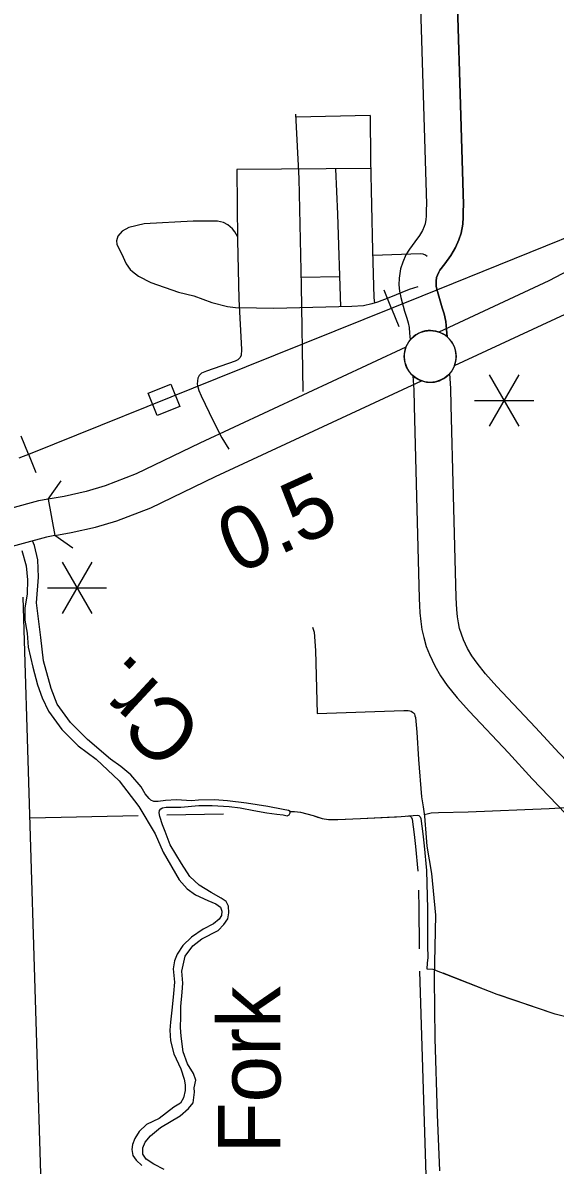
# Model space of a CAD drawing. Extents: x 1084508 to 1142749, y 1057638 to 1093403.
# Drawn here: x 1109506 to 1110633, y 1075928 to 1078349 of the extents above; entities that cross this region are included whole.
import ezdxf

# ---------------------------------------------------------------- set-up
doc = ezdxf.new("R2010")
doc.units = 0
for name, color, linetype in [('Level 10', 7, 'Continuous'), ('Level 15', 7, 'Continuous'), ('Level 2', 7, 'Continuous'), ('Level 24', 7, 'Continuous'), ('Level 33', 7, 'Continuous'), ('Level 34', 7, 'Continuous'), ('Level 35', 7, 'Continuous'), ('Level 37', 7, 'Continuous'), ('Level 40', 7, 'Continuous'), ('Level 43', 7, 'Continuous'), ('Level 48', 7, 'Continuous'), ('Level 6', 7, 'Continuous')]:
    doc.layers.add(name, color=color, linetype=linetype)

msp = doc.modelspace()

# ---------------------------------------------------------------- linework, layer by layer
at = {"layer": 'Level 10'}
for p, q in [((1110360.1, 1077952.2), (1110360.1, 1077950.4)), ((1110438.5, 1077948.6), (1110438.5, 1077950.4))]:
    msp.add_line(p, q, dxfattribs=at)
for points in [[(1110347.9, 1078381.2), (1110354.3, 1078172.5), (1110360.6, 1077964.2), (1110360.1, 1077952.2)], [(1110426.3, 1078384.2), (1110432.8, 1078174.9), (1110439.2, 1077963.6), (1110438.5, 1077948.6)], [(1110438.5, 1077948.6), (1110439.2, 1077963.6), (1110432.8, 1078174.9), (1110426.3, 1078384.2)], [(1110360.1, 1077950.4), (1110360.1, 1077939), (1110359.7, 1077932.1), (1110357.9, 1077922.9), (1110355.9, 1077916.8), (1110352.1, 1077908.3), (1110346.1, 1077898.1), (1110336.2, 1077884.3), (1110324.9, 1077869.2), (1110317.1, 1077857.2), (1110310.6, 1077841.6), (1110305.6, 1077827), (1110303, 1077807.7), (1110302.5, 1077793.4), (1110303.8, 1077779.7), (1110306.3, 1077766.4), (1110314.5, 1077737.6), (1110318.8, 1077722.9), (1110321.8, 1077712.6), (1110323.8, 1077703.2), (1110325.1, 1077690.9), (1110326.3, 1077676.6)], [(1110438.5, 1077950.4), (1110438.5, 1077936.7), (1110437.7, 1077922.2), (1110434, 1077903.2), (1110429.2, 1077888.5), (1110422, 1077872.5), (1110412.1, 1077855.3), (1110399.4, 1077837.8), (1110389.3, 1077824.2), (1110386.7, 1077820.3), (1110384, 1077813.8), (1110382.3, 1077808.8), (1110381.3, 1077801.2), (1110381.1, 1077796), (1110381.6, 1077790.7), (1110382.8, 1077784.4), (1110389.9, 1077759.3), (1110394.2, 1077744.7), (1110397.9, 1077731.7), (1110401.4, 1077715.5), (1110403.2, 1077698.4), (1110404.5, 1077683.2)], [(1110404.5, 1077683.2), (1110403.2, 1077698.4), (1110401.4, 1077715.5), (1110397.9, 1077731.7), (1110394.2, 1077744.7), (1110389.9, 1077759.3), (1110382.8, 1077784.4), (1110381.6, 1077790.7), (1110381.1, 1077796), (1110381.3, 1077801.2), (1110382.3, 1077808.8), (1110384, 1077813.8), (1110386.7, 1077820.3), (1110389.3, 1077824.2), (1110399.4, 1077837.8), (1110412.1, 1077855.3), (1110422, 1077872.5), (1110429.2, 1077888.5), (1110434, 1077903.2), (1110437.7, 1077922.2), (1110438.5, 1077936.7), (1110438.5, 1077950.4)], [(1110331.9, 1077600.8), (1110333.8, 1077570.7), (1110334.4, 1077535.9), (1110339.6, 1077344.8), (1110345.4, 1077128.6), (1110345.7, 1077113.8), (1110346.7, 1077098.3), (1110348.7, 1077080), (1110351.1, 1077063.1), (1110354.8, 1077045.6), (1110360.4, 1077027.1), (1110367.2, 1077009.8), (1110378.2, 1076986), (1110390.6, 1076964.7), (1110404.8, 1076944.3), (1110425.6, 1076918.2), (1110451.8, 1076889.2), (1110534.2, 1076801.5), (1110584.8, 1076746.7), (1110673.9, 1076653.8), (1110852.9, 1076463), (1111028.2, 1076276), (1111170.9, 1076126.4)], [(1111170.9, 1076126.4), (1111167.8, 1076243.4), (1111085.2, 1076329.9), (1110910.1, 1076516.7), (1110730.8, 1076707.9), (1110641.9, 1076800.4), (1110591.6, 1076855), (1110509.5, 1076942.3), (1110485.5, 1076968.9), (1110467.8, 1076991.2), (1110456.9, 1077006.9), (1110447.9, 1077022.3), (1110439.3, 1077040.7), (1110434.6, 1077052.8), (1110430.9, 1077064.9), (1110428.5, 1077076.7), (1110426.6, 1077089.8), (1110424.9, 1077105.2), (1110424.1, 1077117.2), (1110423.8, 1077130.5), (1110418, 1077346.9), (1110412.8, 1077537.6), (1110412.2, 1077573.8), (1110410.2, 1077605.7)]]:
    msp.add_lwpolyline(points, dxfattribs=at)
for start, end in [(49.2235, 140.3932), (228.0122, 319.182)]:
    msp.add_arc((1110368.6, 1077641.6), 54.9, start, end, dxfattribs=at)
at = {"layer": 'Level 15'}
msp.add_line((1109559.6, 1077339.2), (1109573.2, 1077261.9), dxfattribs=at)
for points in [[(1118020.1, 1080804.8), (1117454.8, 1080577.1), (1116519.3, 1080199.4), (1116394.7, 1080147.6), (1116308.1, 1080104.8), (1116151.2, 1080024.8), (1116076, 1079990.7), (1115983.7, 1079954.5), (1115857.6, 1079915.5), (1115726, 1079874.6), (1115624.4, 1079837.7), (1114621, 1079433.2), (1113651.5, 1079041.6), (1112659, 1078640), (1111665.4, 1078240.4), (1110770, 1077877.8), (1110703.6, 1077845.6), (1110619.8, 1077801.6), (1110387, 1077693.4)], [(1110420, 1077622.2), (1110654.6, 1077731.3), (1110738.9, 1077775.5), (1110801.9, 1077806.1), (1111694.8, 1078167.6), (1112688.3, 1078567.2), (1113680.9, 1078968.8), (1114650.4, 1079360.4), (1115652.5, 1079764.4), (1115751, 1079800.2), (1115880.8, 1079840.5), (1116009.6, 1079880.4), (1116106.5, 1079918.4), (1116185.3, 1079954.1), (1116343.3, 1080034.7), (1116427.2, 1080076.1), (1116549, 1080126.8), (1117484.2, 1080504.3), (1118049.4, 1080732)], [(1110317.2, 1077661), (1109880.3, 1077457.9), (1109745.8, 1077392.6), (1109679.8, 1077367.7), (1109639.5, 1077355.5), (1109592.9, 1077345.1), (1109559.6, 1077339.2)], [(1109573.2, 1077261.9), (1109608.3, 1077268.1), (1109659.5, 1077279.6), (1109705, 1077293.4), (1109776.9, 1077320.4), (1109914, 1077387), (1110350.3, 1077589.8)], [(1109559.6, 1077339.2), (1109538.7, 1077335.5), (1109344.5, 1077282.5)], [(1109573.2, 1077261.9), (1109555.8, 1077258.8), (1109365.1, 1077206.8)]]:
    msp.add_lwpolyline(points, dxfattribs=at)
for start, end in [(339.3435, 70.5125), (159.3433, 250.5128)]:
    msp.add_arc((1110368.6, 1077641.6), 54.9, start, end, dxfattribs=at)
at = {"layer": 'Level 2'}
msp.add_lwpolyline([(1109611.1, 1072552.7), (1109576.8, 1074143.1), (1109546.8, 1075817.6), (1109506.3, 1077131.6)], dxfattribs=at)
at = {"layer": 'Level 24'}
msp.add_circle((1110368.6, 1077641.6), 54.9, dxfattribs=at)
at = {"layer": 'Level 33'}
for points in [[(1110083.4, 1078155), (1110090.3, 1078019), (1110095.2, 1077791), (1110098.8, 1077568.2), (1110098.8, 1077567.5)], [(1110241.3, 1078152.6), (1110083.7, 1078148.6)], [(1110241.3, 1078152.6), (1110242.2, 1078058.6), (1110246.6, 1077866.2), (1110249.1, 1077766.3), (1110250.3, 1077754.4)], [(1109959, 1078038.1), (1109960.4, 1077888.2), (1109963.3, 1077763.2), (1109968.9, 1077656.6), (1109968, 1077643.6), (1109965, 1077638.5), (1109960.8, 1077634.5), (1109955.4, 1077631.5), (1109894.5, 1077610.5)], [(1110242.6, 1078039.6), (1109959, 1078038.1)], [(1110179.2, 1077746.8), (1110173.1, 1077942.9), (1110168.8, 1078039.2)], [(1110362.3, 1077853.6), (1110358.4, 1077856.2), (1110353.7, 1077858.1), (1110347.9, 1077858.8), (1110246.8, 1077855.9)], [(1110094.8, 1077809.3), (1110177.2, 1077810.7)], [(1110342.4, 1077788.8), (1110323.8, 1077783.5), (1110280.7, 1077765.5), (1110257.2, 1077756.4), (1110244.9, 1077752.8), (1110227.4, 1077749.2), (1110202.5, 1077747.4), (1110037.2, 1077743), (1109963.9, 1077744.6)]]:
    msp.add_lwpolyline(points, dxfattribs=at)
at = {"layer": 'Level 34'}
for points in [[(1109960.3, 1077896), (1109954.6, 1077906), (1109949.6, 1077912.1), (1109939.9, 1077920.7), (1109930.6, 1077925.4), (1109918.1, 1077928.6), (1109866.5, 1077928.2), (1109762.6, 1077922.9), (1109730.4, 1077914.6), (1109716.1, 1077907.1), (1109706.8, 1077896.7), (1109704.2, 1077886.7), (1109705, 1077879.9), (1109708.2, 1077872), (1109714.3, 1077859.8), (1109724.7, 1077837.9), (1109732.9, 1077825.8), (1109737.6, 1077821.5), (1109750.8, 1077811.8), (1109777, 1077798.2), (1109835.3, 1077777.7), (1109867.9, 1077770.2), (1109906.3, 1077756.2), (1109939.2, 1077747.6), (1109956, 1077745.5), (1109963.9, 1077744.6)], [(1109894.5, 1077610.5), (1109883.9, 1077606.2), (1109879.3, 1077601.4), (1109876.5, 1077595.5), (1109875.4, 1077589.6), (1109875.1, 1077582.8), (1109876.2, 1077577.2), (1109878.8, 1077569.1), (1109883.7, 1077558), (1109900.5, 1077523), (1109921.4, 1077479.8), (1109927.4, 1077469.1), (1109942, 1077444.9)], [(1110119.6, 1077068.1), (1110123.1, 1077057.3), (1110125.9, 1077018.6), (1110129.2, 1076884.7), (1110312.7, 1076891.2), (1110322.1, 1076891.2), (1110325.8, 1076890.8), (1110328.2, 1076889.6), (1110331.1, 1076888), (1110333.1, 1076886.3), (1110335.2, 1076883.9), (1110336.4, 1076880.2), (1110337.6, 1076876.1), (1110340.1, 1076845.1), (1110344, 1076787.5), (1110350.1, 1076708.3), (1110353.4, 1076686.7), (1110356.2, 1076667.5), (1110359.9, 1076621.8), (1110361.5, 1076603.5), (1110371.3, 1076546), (1110379.5, 1076457.4), (1110377, 1076323.1), (1110378.5, 1076195.9), (1110383.3, 1076035.2), (1110388.4, 1075915.2)], [(1110688, 1076695.8), (1110684.3, 1076692.1), (1110679.2, 1076688.9), (1110673, 1076686.5), (1110666.6, 1076685.7), (1110656.1, 1076684.6), (1110620.9, 1076682.5), (1110448.7, 1076676), (1110386.3, 1076674.1), (1110371, 1076673.3), (1110362.1, 1076671.7), (1110355.8, 1076670.3)]]:
    msp.add_lwpolyline(points, dxfattribs=at)
at = {"layer": 'Level 35'}
for points in [[(1109804.9, 1075918.5), (1109783.3, 1075929.3), (1109766.7, 1075940.2), (1109759.9, 1075951), (1109759.9, 1075964.1), (1109764.5, 1075976.1), (1109776.4, 1075989.8), (1109797.5, 1076007.4), (1109839.1, 1076031.9), (1109856.8, 1076047.9), (1109866.5, 1076059.3), (1109869.3, 1076082.1), (1109868.7, 1076091.4), (1109872.2, 1076108), (1109867, 1076121.6), (1109854.5, 1076142.2), (1109845.4, 1076167.8), (1109840.8, 1076200.9), (1109839.7, 1076219.1), (1109840.2, 1076241.9), (1109840.2, 1076263.6), (1109843.1, 1076294.4), (1109844.8, 1076313.2), (1109842.5, 1076338.9), (1109849.4, 1076370.8), (1109865.9, 1076392.5), (1109884.7, 1076407.3), (1109919.5, 1076425), (1109931.4, 1076437.5), (1109940, 1076449.5), (1109941.7, 1076462.6), (1109941.1, 1076476.3), (1109936.6, 1076486.5), (1109925.7, 1076493.4), (1109904.6, 1076505.3), (1109879, 1076521.3), (1109859.1, 1076539.6), (1109842, 1076566.9), (1109818, 1076606.8), (1109807.2, 1076634.8), (1109801.5, 1076649), (1109795.8, 1076666.7), (1109794.5, 1076674.3), (1109795.1, 1076679.1), (1109797.7, 1076682.5), (1109801.4, 1076684.8), (1109809, 1076686.2), (1109840.1, 1076686.2), (1109878.3, 1076689.6), (1109906.8, 1076689.6), (1109942.4, 1076687.4), (1109965.8, 1076684.8), (1109995.2, 1076679.4), (1110022.3, 1076674.3), (1110043.4, 1076671.4), (1110056.8, 1076670), (1110065.9, 1076667.7), (1110069.6, 1076670), (1110071.6, 1076674), (1110071.6, 1076677.1), (1110068.5, 1076679.4), (1110057.1, 1076681.7), (1110024.3, 1076687.7), (1109979.3, 1076694.8), (1109939.1, 1076699.9), (1109912, 1076701.6), (1109878.1, 1076700.8), (1109862.7, 1076699.9), (1109831.4, 1076701.9), (1109808.2, 1076700.5), (1109792, 1076698.5), (1109782.8, 1076698.5), (1109776.6, 1076700.8), (1109772.9, 1076704.8), (1109764.9, 1076714.4), (1109756.6, 1076729.3), (1109734.7, 1076754.6), (1109713, 1076772.3), (1109691.1, 1076788.3), (1109642.8, 1076830), (1109606.9, 1076866), (1109578.4, 1076904.7), (1109565.9, 1076937.8), (1109549.3, 1076996.5), (1109543.6, 1077045.6), (1109534.5, 1077119.1), (1109538.5, 1077173.8), (1109537.4, 1077210.3), (1109530, 1077241.2), (1109526.4, 1077250.6)], [(1109503.2, 1077230.6), (1109512.9, 1077197.5), (1109515.2, 1077167.9), (1109514.6, 1077138.8), (1109510, 1077108.4), (1109509.5, 1077082.8), (1109514.6, 1077055.4), (1109516.9, 1077025.7), (1109527.1, 1076983), (1109536.8, 1076945.9), (1109546.5, 1076918), (1109560.2, 1076889.5), (1109588.1, 1076850.7), (1109622.9, 1076816.5), (1109661.3, 1076787.8), (1109709.8, 1076742.2), (1109751.4, 1076687.5), (1109786.1, 1076629.9), (1109802.7, 1076591.1), (1109836.9, 1076532.4), (1109854, 1076513.4), (1109871.1, 1076500.8), (1109897.8, 1076488.3), (1109914.4, 1076481.4), (1109924.6, 1076474), (1109926.9, 1076466), (1109926.3, 1076456.9), (1109921.2, 1076448.9), (1109909.8, 1076439.2), (1109887.6, 1076427.8), (1109863.1, 1076410.7), (1109844.8, 1076393.1), (1109832.9, 1076374.8), (1109826.6, 1076360.6), (1109823.8, 1076343.5), (1109826.6, 1076315.5), (1109824.9, 1076291.6), (1109822, 1076262.3), (1109818.1, 1076230.9), (1109816.9, 1076213.8), (1109818.1, 1076191), (1109825.5, 1076163.6), (1109840.3, 1076131.7), (1109847.7, 1076109.5)], [(1109847.7, 1076109.5), (1109849.4, 1076097.5), (1109849.4, 1076085.5), (1109846, 1076070.1), (1109839.7, 1076059.2), (1109825.5, 1076050.6), (1109794.1, 1076026.7), (1109767.9, 1076013.6), (1109751.9, 1075998.7), (1109742.8, 1075983.9), (1109737.7, 1075971.4), (1109736.6, 1075960.5), (1109738.3, 1075948), (1109745.7, 1075938.3), (1109757.6, 1075926.9)]]:
    msp.add_lwpolyline(points, dxfattribs=at)
at = {"layer": 'Level 37'}
for points in [[(1109559.6, 1077339.2), (1109586.6, 1077377.7)], [(1109611.8, 1077234.9), (1109573.2, 1077261.9)]]:
    msp.add_lwpolyline(points, dxfattribs=at)
at = {"layer": 'Level 40'}
for p, q in [((1110286.6, 1077743.5), (1110271.1, 1077781.9)), ((1110286.6, 1077743.5), (1110302, 1077705)), ((1109517.8, 1077434.2), (1109502.3, 1077472.6)), ((1109517.8, 1077434.2), (1109533.4, 1077395.8))]:
    msp.add_line(p, q, dxfattribs=at)
msp.add_lwpolyline([(1114164.2, 1079308.5), (1113746.2, 1079140.3), (1113322.1, 1078969), (1112887, 1078794.2), (1112466, 1078623.7), (1112227.5, 1078528), (1112039.2, 1078452), (1111631.7, 1078288.6), (1111182.3, 1078105.9), (1110742, 1077927.6), (1110351.1, 1077769.4), (1109917.3, 1077595), (1109521.2, 1077435.5), (1109497, 1077425.7)], dxfattribs=at)
msp.add_lwpolyline([(1114164.2, 1079308.5), (1113746.2, 1079140.3), (1113322.1, 1078969), (1112887, 1078794.2), (1112466, 1078623.7), (1112227.5, 1078528), (1112039.2, 1078452), (1111631.7, 1078288.6), (1111182.3, 1078105.9), (1110742, 1077927.6), (1110351.1, 1077769.4), (1109917.3, 1077595), (1109521.2, 1077435.5), (1109497, 1077425.7)], dxfattribs=at)
msp.add_lwpolyline([(1109790.5, 1077516.3), (1109771.3, 1077563.9), (1109818.9, 1077583), (1109838, 1077535.5)], close=True, dxfattribs=at)
at = {"layer": 'Level 43'}
for points in [[(1110071.6, 1076677.1), (1110081.2, 1076677), (1110093.9, 1076675.4), (1110120.7, 1076668.5), (1110139.9, 1076662.2), (1110153.1, 1076660.3), (1110172.4, 1076660), (1110221.3, 1076662.2), (1110307.4, 1076666.3), (1110341.1, 1076669.1), (1110344.6, 1076668.5), (1110347.1, 1076666), (1110348.7, 1076662.5), (1110352.8, 1076630), (1110355.9, 1076604.5), (1110360.7, 1076552.4), (1110362.9, 1076471), (1110363.2, 1076392.4), (1110363.8, 1076367.8), (1110362.5, 1076355.8), (1110361.3, 1076343.5), (1110374.5, 1076342.9), (1110509.8, 1076290.2), (1110630.3, 1076248.7), (1110682, 1076236.1)], [(1110071.6, 1076677.1), (1110081.2, 1076677), (1110093.9, 1076675.4), (1110120.7, 1076668.5), (1110132.1, 1076664.7)], [(1110173, 1076660), (1110221.3, 1076662.2), (1110297.2, 1076665.8)], [(1110320.2, 1076667.4), (1110322.7, 1076667.7), (1110326.2, 1076667), (1110328.7, 1076664.5), (1110330.3, 1076661), (1110334.4, 1076628.5), (1110337.6, 1076603), (1110342.3, 1076550.9), (1110342.3, 1076550.9)], [(1110343.6, 1076510.5), (1110344.6, 1076470.7), (1110345, 1076392.2), (1110345.1, 1076386.2)], [(1110395.1, 1076334.9), (1110476.2, 1076303.3)], [(1110514.9, 1076288.4), (1110630.3, 1076248.7), (1110632.5, 1076248.2)]]:
    msp.add_lwpolyline(points, dxfattribs=at)
at = {"layer": 'Level 48'}
for p, q in [((1110556.5, 1077602.3), (1110493.7, 1077493.5)), ((1110493.7, 1077602.3), (1110556.5, 1077493.5)), ((1110462.3, 1077547.9), (1110587.9, 1077547.9)), ((1109651.7, 1077205.6), (1109589, 1077096.9)), ((1109589, 1077205.6), (1109651.7, 1077096.9)), ((1109557.6, 1077151.2), (1109683.1, 1077151.2))]:
    msp.add_line(p, q, dxfattribs=at)
at = {"layer": 'Level 6'}
for points in [[(1109930.7, 1076671.5), (1109811, 1076669.1)], [(1109750.1, 1076667.9), (1109520.8, 1076663.3)], [(1110362.4, 1075838.1), (1110346.9, 1076338.4)]]:
    msp.add_lwpolyline(points, dxfattribs=at)

# ---------------------------------------------------------------- texts
at = {"layer": 'Level 35'}
for s, rotation, p in [('Cr.', 137.1861, (1109894.7, 1076855.8)), ('Fork', 90, (1110051.4, 1075952.1))]:
    msp.add_text(s, height=132.58, rotation=rotation, dxfattribs=at).set_placement(p)
at = {"layer": 'Level 48'}
msp.add_text('0.5', height=132.58, rotation=24.5779, dxfattribs=at).set_placement((1109958.8, 1077178.5))

doc.saveas('drawing.dxf')
